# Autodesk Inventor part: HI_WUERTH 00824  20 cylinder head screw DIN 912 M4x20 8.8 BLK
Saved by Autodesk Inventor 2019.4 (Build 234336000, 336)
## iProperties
Created: 2021-08
Part Number: HI_WUERTH 00824  20 cylinder head screw DIN 912 M4x20 8.8 BLK
Material: Generic
Document SubType Name: Modeling
Designer: Administrator
Density: 1 g/cm^3
Appearance: Default
Title: HI_WUERTH 00824  20 cylinder head screw DIN 912 M4x20 8.8 BLK
Author: Administrator
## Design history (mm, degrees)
feature "Body1"
body "Solid1"
